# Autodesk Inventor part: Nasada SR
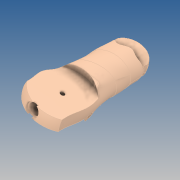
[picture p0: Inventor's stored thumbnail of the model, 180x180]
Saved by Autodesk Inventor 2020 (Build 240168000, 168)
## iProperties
Created: 2019-10
Part Number: Nasada SR
Material: GFRP
Document SubType Name: Modeling
Designer: yello
Density: 1.75 g/cm^3
Appearance: Default
Author: yello
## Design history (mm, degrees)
feature "Nasada SR"
workplane "Work Plane1"
sketch "Sketch1"
  geometry: L1 (-3.5, 0.006)-(-3.532, -19.994); L2 (-3.532, -19.994)-(3.468, -20.006); L3 (3.468, -20.006)-(3.5, -0.006); L4 (3.5, -0.006)-(3.548, 29.994); L5 (3.548, 29.994)-(-3.452, 30.006); L6 (-3.452, 30.006)-(-3.5, 0.006); L7 (0.048, 30)-(-0.032, -20); A1 r 3.5 centre (0, 0) between (-3.5, 0.006) and (3.5, -0.006); 1 further point
  constraints: 14 end point, 3 perpendicular, 2 midpoint, 2 point on circle, 2 point on line, 2 tangent, 1 centre point
  dimensions: "d0" = 7 diameter of A1; "d1" = 20 distance of L1.start L1.end; "d2" = 30 distance of L3.end L4.end
revolve "Revolution1" sketch "Sketch1" stored, may be unused: angle "d3" = 90 deg
workplane "Work Plane2"
sketch "Sketch2"
  geometry: C1 r 4.25 at (0, 0)
  constraints: 1 centre point
  dimensions: "d5" = 8.5 diameter of C1
extrude "Extrusion1" cut sketch "Sketch2" distance "d6" = 1.75; taper "d7" = 0 deg
workplane "Work Plane3"
sketch "Sketch3"
  geometry: L1 (-3.101, 29.402)-(-9.983, 30.68) reference; L2 (-18.43, -14.792)-(-11.548, -16.07) reference; L3 (-6.542, 30.041)-(-12.021, 0.546); L4 (-12.021, 0.546)-(-12.675, -2.975); C1 r 1.5 at (-12.021, 0.546); 3 further points
  constraints: 4 end point, 1 centre point, 1 coincident, 1 midpoint, 1 perpendicular
  dimensions: "d9" = 30 distance of L3.start L3.end; "d10" = 3 diameter of C1
revolve "Revolution2" sketch "Sketch3" stored, may be unused: angle "d11" = 90 deg
mirror "Mirror1"
workplane "Work Plane4"
sketch "Sketch5"
  geometry: L1 (28.5, -7)-(28.5, 0) reference; L2 (28.5, -3.5)-(24.75, -3.5); L3 (24.75, -3.5)-(16.5, -3.5); L4 (24.75, -2.5)-(16.5, -2.5); L5 (16.5, -4.5)-(24.75, -4.5); A1 r 1 centre (24.75, -3.5) between (24.75, -4.5) and (24.75, -2.5); A2 r 1 centre (16.5, -3.5) between (16.5, -2.5) and (16.5, -4.5); 2 further points
  constraints: 10 end point, 4 point on circle, 4 tangent, 2 centre point, 2 horizontal, 2 midpoint, 1 parallel
  dimensions: "d15" = 3.75 distance of L2.start L2.end; "d16" = 8.25 distance of L2.end L3.end; "d17" = 2 diameter of A2
extrude "Extrusion3" cut sketch "Sketch5" distance "d18" = 324; taper "d19" = 0 deg
body "Solid1"
other parameters: "sa_0" = 4, "d4" = 48, "d8" = -0.5
